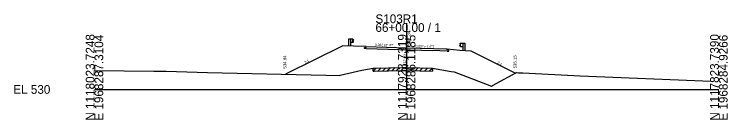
# Model space of a CAD drawing. Extents: x -26 to 203, y -10 to 12018.
# Drawn here: x -25.7 to 202.8, y 6490.3 to 6524 of the extents above; entities that cross this region are included whole.
import ezdxf

# ---------------------------------------------------------------- set-up
doc = ezdxf.new("R2010")
doc.units = 0
for name, color, linetype in [('Level 10', 7, 'Continuous'), ('Level 11', 7, 'Continuous'), ('Level 12', 7, 'Continuous'), ('Level 24', 7, 'Continuous'), ('Level 32', 7, 'Continuous'), ('Level 33', 7, 'Continuous'), ('Level 59', 7, 'Continuous'), ('Level 6', 7, 'Continuous'), ('Level 60', 7, 'Continuous'), ('Level 61', 7, 'Continuous'), ('Level 63', 7, 'Continuous'), ('Level 7', 7, 'Continuous')]:
    doc.layers.add(name, color=color, linetype=linetype)

msp = doc.modelspace()

# ---------------------------------------------------------------- linework, layer by layer
at = {"layer": 'Level 11'}
for p, q in [((86.5, 6513.45), (87, 6513.43)), ((86.5, 6513.09), (86.5, 6513.45)), ((87, 6513.43), (87, 6513.75)), ((87, 6513.07), (86.5, 6513.09)), ((113, 6512.61), (113, 6512.93)), ((113.5, 6512.6), (113, 6512.61)), ((113, 6512.25), (113.5, 6512.24)), ((113.5, 6512.24), (113.5, 6512.6))]:
    msp.add_line(p, q, dxfattribs=at)
at = {"layer": 'Level 12'}
for p in [(87, 6513.07), (113, 6512.25)]:
    msp.add_line(p, (108.23, 6512.4), dxfattribs=at)
at = {"layer": 'Level 24'}
for p, q in [((81.4, 6516.12), (81.4, 6513.92)), ((82.06, 6516.12), (81.4, 6516.12)), ((82.06, 6516.12), (82.06, 6513.9)), ((82.73, 6516.12), (82.06, 6516.12)), ((82.73, 6514.96), (82.73, 6516.12)), ((82.73, 6516.05), (83, 6515.85)), ((83, 6515.8), (82.73, 6515.6)), ((83, 6515.28), (82.73, 6515.48)), ((83, 6515.85), (83, 6515.8)), ((82.73, 6514.96), (82.06, 6514.96)), ((82.73, 6515.03), (83, 6515.23)), ((83, 6515.23), (83, 6515.28)), ((117.27, 6514.77), (117, 6514.57)), ((117, 6514.57), (117, 6514.52)), ((117, 6514.52), (117.27, 6514.32)), ((117, 6514), (117.27, 6514.2)), ((117, 6513.95), (117, 6514)), ((117.27, 6513.75), (117, 6513.95)), ((117.27, 6513.68), (117.27, 6514.84)), ((117.27, 6514.84), (117.94, 6514.84)), ((117.27, 6513.68), (117.94, 6513.68)), ((117.94, 6514.84), (117.94, 6512.51)), ((117.94, 6514.84), (118.6, 6514.84)), ((118.6, 6514.84), (118.6, 6512.46))]:
    msp.add_line(p, q, dxfattribs=at)
at = {"layer": 'Level 59'}
for p, q in [((87, 6513.75), (100, 6513.34)), ((100, 6513.34), (113, 6512.93))]:
    msp.add_line(p, q, dxfattribs=at)
at = {"layer": 'Level 6'}
for p, q in [((83, 6513.87), (79.5, 6513.98)), ((87, 6513.75), (83, 6513.87)), ((113, 6512.93), (117, 6512.59)), ((117, 6512.59), (120.5, 6512.3))]:
    msp.add_line(p, q, dxfattribs=at)
at = {"layer": 'Level 60'}
for p, q in [((85.67, 6506.19), (89.25, 6506.79)), ((89.25, 6506.79), (89.55, 6506.8)), ((89.55, 6506.8), (98.78, 6507.06)), ((98.78, 6507.06), (99.33, 6507.05)), ((99.33, 6507.05), (100, 6507.03)), ((100, 6507.03), (108.23, 6506.79)), ((108.23, 6506.79), (114.22, 6505.77)), ((0, 6506.06), (19.05, 6505.88)), ((19.05, 6505.88), (22.95, 6505.79)), ((22.95, 6505.79), (36.16, 6505.43)), ((36.16, 6505.43), (74.11, 6504.53)), ((74.11, 6504.53), (78.37, 6504.44)), ((78.37, 6504.44), (78.72, 6504.53)), ((78.72, 6504.53), (85.67, 6506.19)), ((114.22, 6505.77), (115.18, 6505.61)), ((115.18, 6505.61), (127.16, 6501.04)), ((127.52, 6501.23), (135.23, 6505.38)), ((135.23, 6505.38), (135.77, 6505.3)), ((135.77, 6505.3), (137.25, 6505.27)), ((137.25, 6505.27), (155.59, 6504.32)), ((155.59, 6504.32), (197.5, 6502.64)), ((127.16, 6501.04), (127.52, 6501.23))]:
    msp.add_line(p, q, dxfattribs=at)
at = {"layer": 'Level 61'}
for p, q in [((89.25, 6505.79), (90.28, 6506.82)), ((89.25, 6505.79), (89.25, 6506.79)), ((90.75, 6505.83), (91.78, 6506.86)), ((92.25, 6505.87), (93.28, 6506.9)), ((93.75, 6505.92), (94.78, 6506.95)), ((95.25, 6505.96), (96.28, 6506.99)), ((96.75, 6506), (97.78, 6507.03)), ((98.25, 6506.05), (99.25, 6507.05)), ((99.75, 6506.03), (100.72, 6507.01)), ((101.25, 6505.99), (102.22, 6506.96)), ((102.75, 6505.95), (103.72, 6506.92)), ((104.25, 6505.9), (105.22, 6506.87)), ((105.75, 6505.86), (106.72, 6506.83)), ((107.25, 6505.82), (108.22, 6506.79)), ((108.23, 6506.79), (108.23, 6505.79)), ((89.25, 6505.79), (89.55, 6505.8)), ((89.55, 6505.8), (98.78, 6506.06)), ((98.78, 6506.06), (99.33, 6506.05)), ((99.33, 6506.05), (100, 6506.03)), ((100, 6506.03), (108.23, 6505.79))]:
    msp.add_line(p, q, dxfattribs=at)
at = {"layer": 'Level 63'}
for p, q in [((100, 6500), (100, 6521.19)), ((0, 6500), (100, 6500)), ((100, 6500), (200, 6500))]:
    msp.add_line(p, q, dxfattribs=at)
at = {"layer": 'Level 7'}
for p, q in [((79.5, 6513.98), (61.21, 6504.84)), ((120.5, 6512.3), (134.81, 6505.15))]:
    msp.add_line(p, q, dxfattribs=at)

# ---------------------------------------------------------------- texts
at = {"layer": 'Level 10'}
msp.add_text(' 537.03', height=0.9, rotation=90, dxfattribs=at).set_placement((99.95, 6507.17))
at = {"layer": 'Level 32'}
for s, rotation, p in [('0.032 FT./FT.', 358.1901, (89.84, 6513.91)), ('0.032 FT./FT.', 358.1901, (102.84, 6513.5)), ('2:1', 26.5651, (67.5, 6508.26)), ('2:1', 333.4349, (129.04, 6508.31))]:
    msp.add_text(s, height=0.75, rotation=rotation, dxfattribs=at).set_placement(p)
at = {"layer": 'Level 33'}
for s, p in [('534.84', (61.46, 6506.64)), ('535.15', (135.22, 6506.72))]:
    msp.add_text(s, height=1, rotation=90, dxfattribs=at).set_placement(p)
at = {"layer": 'Level 59'}
msp.add_text(' 543.34', height=1.2, rotation=90, dxfattribs=at).set_placement((101.2, 6513.34))
at = {"layer": 'Level 63'}
for s, p in [('S103R1', (90, 6521.19)), ('66+00.00 / 1', (90, 6518.39)), ('EL 530', (-26, 6498.6))]:
    msp.add_text(s, height=2.8, dxfattribs=at).set_placement(p)
for s, p in [('N 1118023.7248', (0, 6490)), ('E 1968287.3104', (2.8, 6490)), ('N 1117923.7319', (100, 6490)), ('E 1968286.1185', (102.8, 6490)), ('N 1117823.7390', (200, 6490)), ('E 1968284.9266', (202.8, 6490))]:
    msp.add_text(s, height=2.8, rotation=90, dxfattribs=at).set_placement(p)

doc.saveas('drawing.dxf')
